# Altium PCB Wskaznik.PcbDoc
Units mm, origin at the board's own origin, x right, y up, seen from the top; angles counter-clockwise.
Board outline 100 x 60 mm, 2 copper layers (Top Layer, Bottom Layer); 40 components, 28 nets, 111 pads, 0 vias.
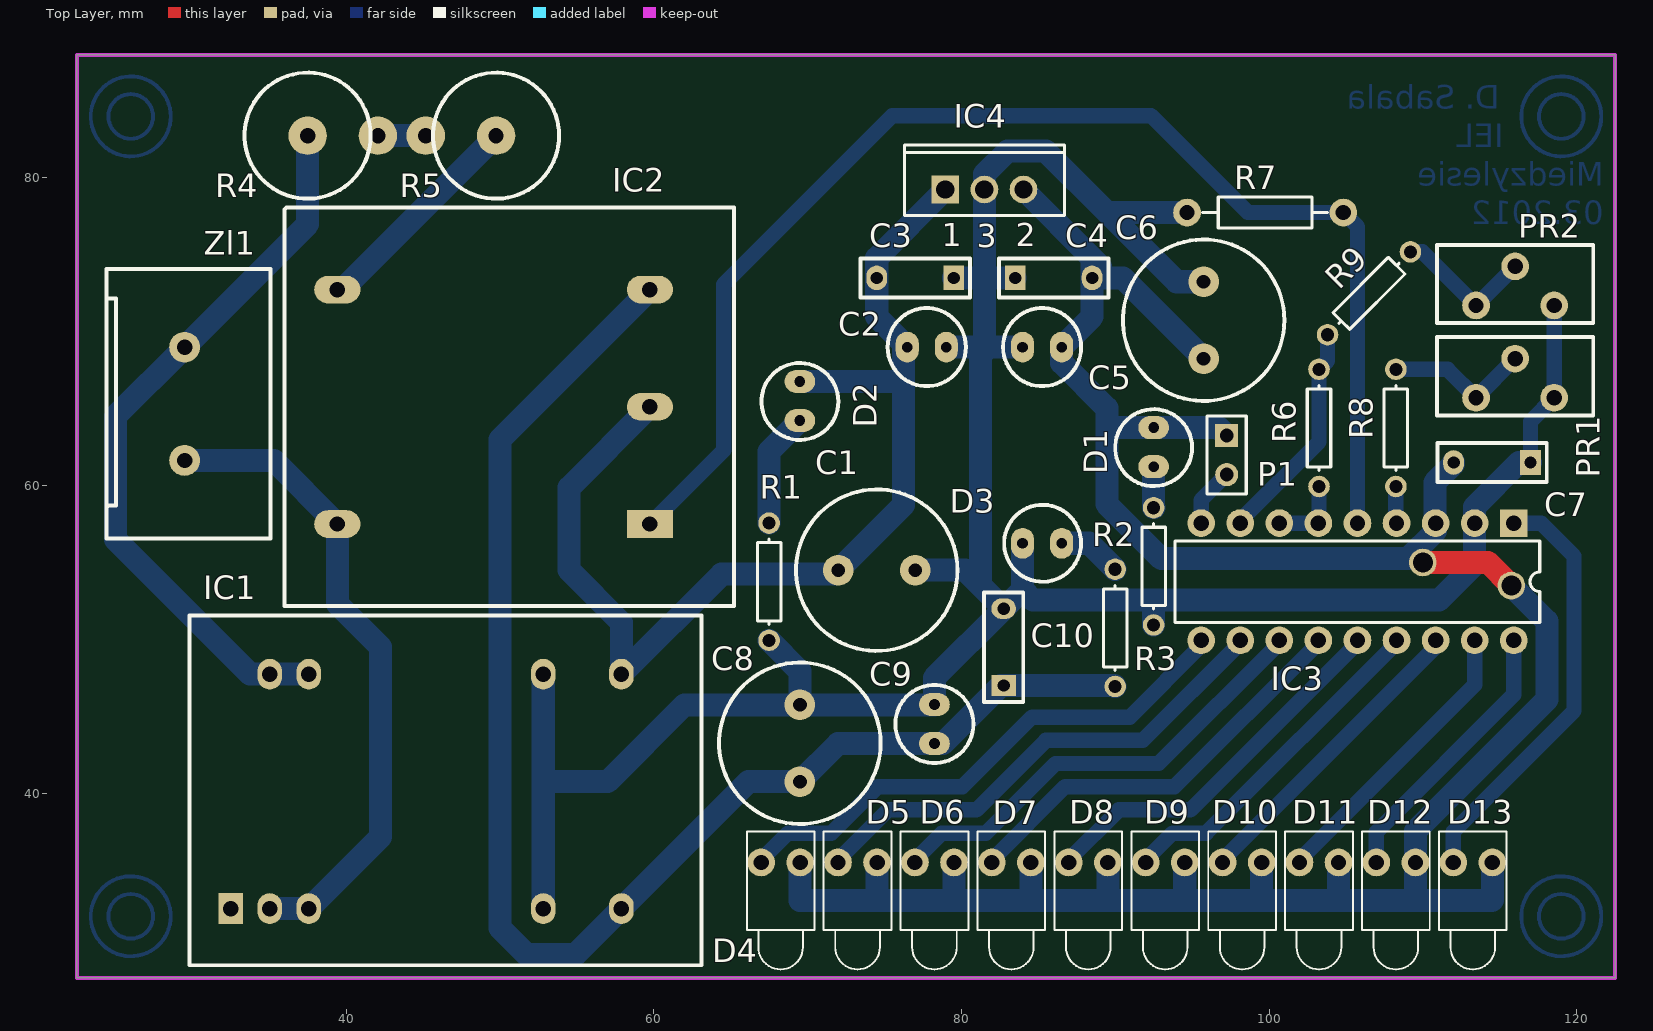
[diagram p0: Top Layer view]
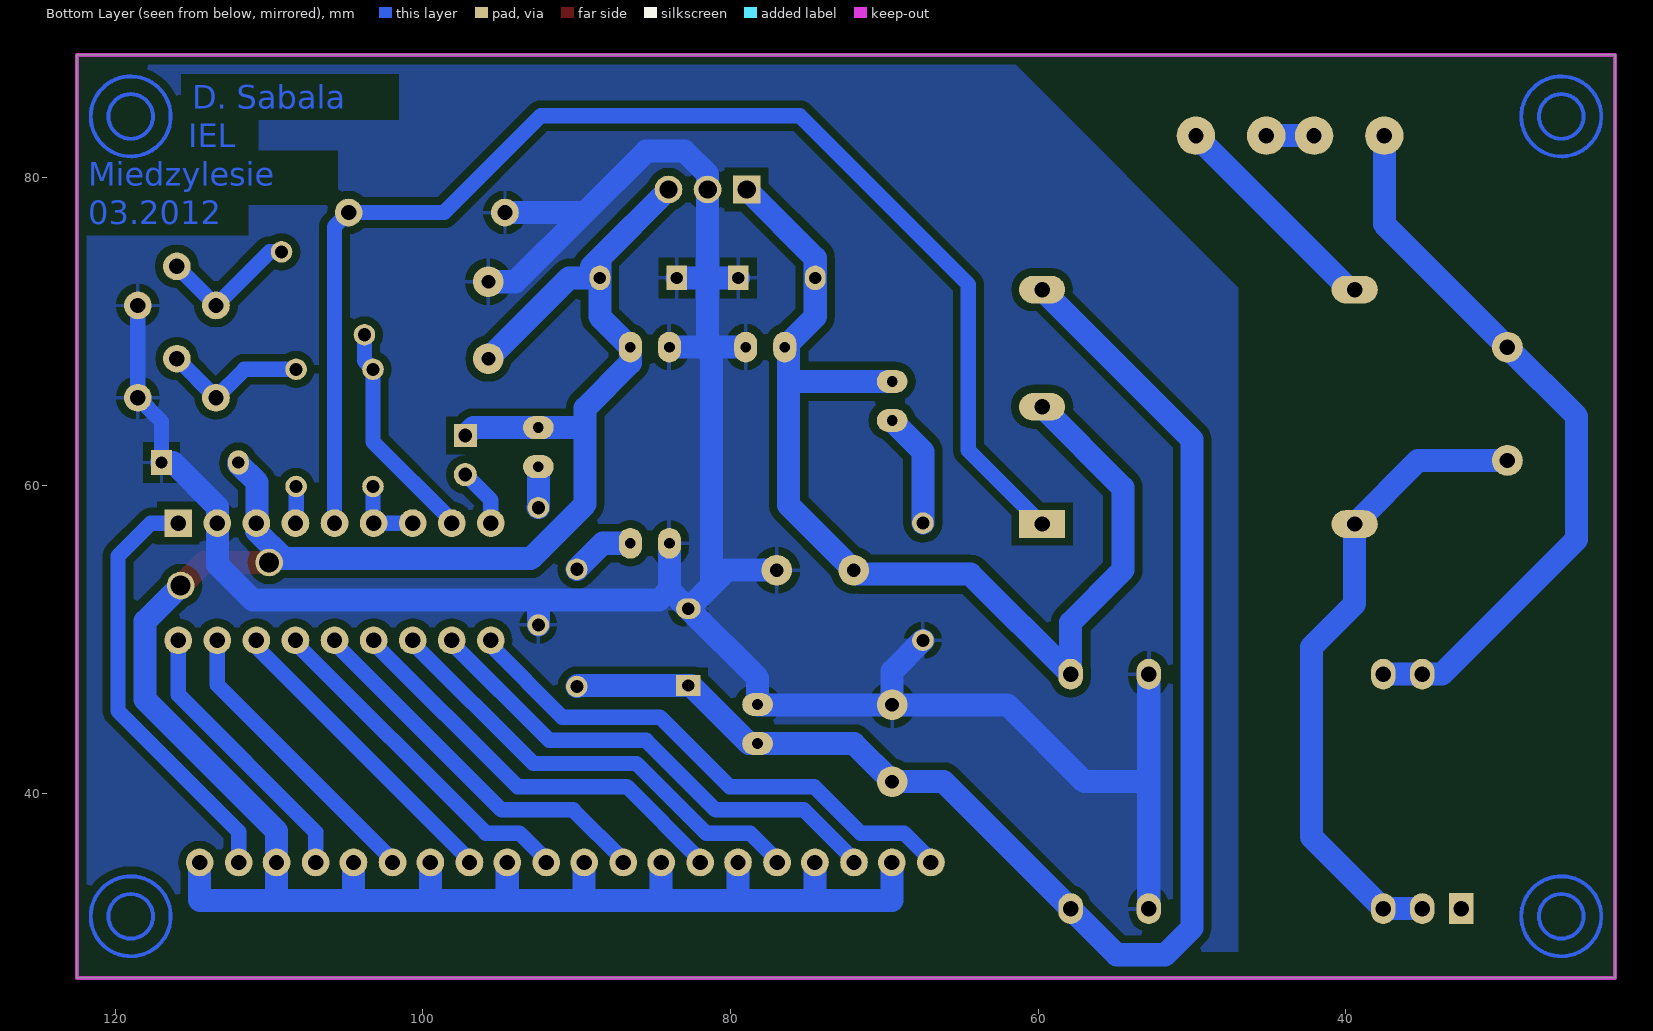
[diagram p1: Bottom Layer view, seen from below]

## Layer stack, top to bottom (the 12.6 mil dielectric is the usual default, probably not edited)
Top Layer: signal copper 0.0356
Dielectric: dielectric 0.32, FR-4, Dk 4.8
Bottom Layer: signal copper 0.0356

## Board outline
22.5,28 22.5,88 122.5,88 122.5,28

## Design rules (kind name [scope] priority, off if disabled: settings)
Clearance [All] p1: gap=0.508
LayerPairs [All] p1 off: enforce=TRUE
PolygonConnect [All] p1: connectstyle=Relief reliefconductorwidth=0.254 reliefentries=4 polygonreliefangle="90 Angle"
RoutingVias [All] p1: holewidth=0.711 width=1.27 viastyle="Through Hole" minholewidth=0.711 minwidth=1.27 maxholewidth=0.711 maxwidth=1.27
SilkscreenOverComponentPads [All] p1: minsilkscreentomaskgap=0.254
SolderMaskExpansion [All] p1: expansion=0.102
Width [All] p1: maxlimit=2 minlimit=0.254 preferedwidth=0.254
26 further rules are at their usual default settings.

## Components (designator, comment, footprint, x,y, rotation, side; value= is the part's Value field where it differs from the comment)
C1 "" RB5-10.5 74.5,54.5 r0 top
C2 "" "Elektrolit 2.5" 77.75,69 r0 top
C3 "" poliestrowy 77,73.5 r180 top
C4 "" poliestrowy 86,73.5 r0 top
C5 "" "Elektrolit 2.5" 85.25,69 r180 top
C6 "" RB5-10.5 95.75,70.75 r90 top
C7 "" poliestrowy 114.5,61.5 r180 top
C8 "" RB5-10.5 69.5,43.25 r270 top
C9 "" "Elektrolit 2.5" 78.25,44.5 r270 top
C10 "" poliestrowy 82.75,49.5 r90 top
D1 "Dioda LED" "dioda led" 92.5,62.5 r270 top
D2 "Dioda LED" "dioda led" 69.5,65.5 r270 top
D3 "Dioda LED" "dioda led" 85.25,56.25 r0 top
D4 "" LED-1 68.25,35.5 r270 top
D5 "" LED-1 73.25,35.5 r270 top
D6 "" LED-1 78.25,35.5 r270 top
D7 "" LED-1 83.25,35.5 r270 top
D8 "" LED-1 88.25,35.5 r270 top
D9 "" LED-1 93.25,35.5 r270 top
D10 "" LED-1 98.25,35.5 r270 top
D11 "" LED-1 103.25,35.5 r270 top
D12 "" LED-1 108.25,35.5 r270 top
D13 "" LED-1 113.25,35.5 r270 top
IC1 "TEN8-7223WI" TRACO-DIP24 32.5,32.5 r90 top
IC2 "LV 25-P" "DIP14 LEM NEW" 59.75,57.5 r180 top
IC3 "LM3914" DIP18 105.75,53.75 r180 top
IC4 "7805" ISOWATT220AB 81.5,79.25 r0 top
P1 "Jumper" HDR1X2 97.25,63.25 r270 top
PR1 "10k" "PCBComponent_1 - duplicate" 116,68.25 r90 top
PR2 "470" "PCBComponent_1 - duplicate" 116,74.25 r90 top
R1 "Rezystor" AXIAL-0.3 67.5,53.75 r90 top
R2 "Rezystor" AXIAL-0.3 92.5,54.75 r90 top
R3 "Rezystor" AXIAL-0.3 90,50.75 r90 top
R4 "Rezystor" "duzy pionowo" 37.5,82.75 r0 top
R5 "Rezystor" "duzy pionowo" 49.75,82.75 r180 top
R6 "Rezystor" AXIAL-0.3 103.25,63.75 r270 top
R7 "" AXIAL-0.4 99.75,77.75 r0 top
R8 "Rezystor" AXIAL-0.3 108.25,63.75 r270 top
R9 "Rezystor" AXIAL-0.3 106.5,72.5 r225 top
Zl1 "Złącze 7.3mm" "PCBComponent_1 - duplicate1" 29.5,69 r270 top

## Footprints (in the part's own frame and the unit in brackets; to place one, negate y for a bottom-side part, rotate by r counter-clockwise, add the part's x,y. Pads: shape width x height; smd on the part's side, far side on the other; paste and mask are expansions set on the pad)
AXIAL-0.3 [mm] "Axial Device, Thru-Hole; 2 Leads; 0.3 in Pin Spacing"
  round 1.4 hole 0.85: 1(-3.81,0) 2(3.81,0)
  silkscreen extent -2.77,-0.76 2.77,0.76
AXIAL-0.4 [mm] "Axial Device, Thru-Hole; 2 Leads; 0.4 in Pin Spacing"
  round 1.8 hole 1 unplated: 1(-5.08,0) 2(5.08,0)
  silkscreen extent -4.06,-1.02 4.06,1.02
"dioda led" [mm] "Radial Cap, Thru-Hole; 2 Leads; 0.1 in Pin Spacing"
  oval 1.5x2 hole 0.7: 1(-1.27,0) 2(1.27,0)
  silkscreen extent -2.47,-2.5 2.53,2.5
"DIP14 LEM NEW" [mm]
  rect 3x1.8 hole 1: 1(0,0)
  oval 3x1.8 hole 1: 4(0,-7.62) 7(0,-15.24) 8(20.32,-15.24) 14(20.32,0)
  silkscreen extent -5.46,-20.57 23.75,5.33
DIP18 [mm] "DIP; 18 Leads; Row Spacing 7.62 mm; Pitch 2.54 mm"
  rect 1.8x1.8 hole 1 unplated: 1(-10.16,-3.81)
  round 1.8 hole 1 unplated: 2(-7.62,-3.81) 3(-5.08,-3.81) 4(-2.54,-3.81) 5(0,-3.81) 6(2.54,-3.81) 7(5.08,-3.81) 8(7.62,-3.81) 9(10.16,-3.81) 10(10.16,3.81) 11(7.62,3.81) 12(5.08,3.81) 13(2.54,3.81) 14(0,3.81) 15(-2.54,3.81) 16(-5.08,3.81) 17(-7.62,3.81) 18(-10.16,3.81)
  silkscreen extent -11.85,-2.65 11.85,2.65
"duzy pionowo" [mm] "Axial Device, Thru-Hole; 2 Leads; 1.0 in Pin Spacing"
  round 2.5 hole 1: 1(0,0) 2(4.572,0)
  silkscreen extent -4.1,-4.1 4.1,4.1
"Elektrolit 2.5" [mm] "raster 2.5mm fi 5.08"
  oval 1.5x2 hole 0.7: 1(-1.27,0) 2(1.27,0)
  silkscreen extent -2.54,-2.54 2.54,2.54
HDR1X2 [mm] "Connector; Header; 2 Position"
  rect 1.5x1.5 hole 0.9: 1(0,0)
  round 1.5 hole 0.9: 2(2.54,0)
  silkscreen extent -1.27,-1.27 3.81,1.27
ISOWATT220AB [mm] "TO, Thru-Hole, Vertical, Heatsink Mounted; 3 In-Line Leads; Pitch 2.54 mm; Pin sequence 1, 3, 2"
  rect 1.8x1.8 hole 1.2: 1(-2.54,0)
  round 1.8 hole 1.2: 2(2.54,0) 3(0,0)
  silkscreen extent -5.2,-1.7 5.2,2.9
LED-1 [mm] "LED; 2 Leads"
  round 1.8 hole 1 unplated: 1(0,1.27) 2(0,-1.27)
  silkscreen extent -2,-2.2 6.95,2.2
"PCBComponent_1 - duplicate" [mm]
  round 1.8 hole 1 unplated: 1(-2.54,-2.54) 2(0,0) 3(-2.54,2.54)
  silkscreen extent -3.68,-5.08 1.4,5.08
"PCBComponent_1 - duplicate1" [mm]
  round 2 hole 1: 1(0,0) 2(7.366,0)
  silkscreen extent -5.08,-5.08 12.45,5.59
poliestrowy [mm] "Capacitor; 2 Leads"
  rect 1.35x1.6 hole 0.8: 1(-2.5,0)
  oval 1.35x1.6 hole 0.8: 2(2.5,0)
  silkscreen extent -3.56,-1.27 3.56,1.27
RB5-10.5 [mm] "Capacitor (Radial); 2 Leads"
  round 2 hole 0.9: 1(-2.5,0) 2(2.5,0)
  silkscreen extent -5.25,-5.25 5.25,5.25
TRACO-DIP24 [mm]
  rect 2x1.6 hole 1 unplated: 1(0,0)
  oval 2x1.6 hole 1 unplated: 2(0,-2.54) 3(0,-5.08) 9(0,-20.32) 11(0,-25.4) 14(15.24,-25.4) 16(15.24,-20.32) 22(15.24,-5.08) 23(15.24,-2.54)
  silkscreen extent -3.68,-30.61 19.05,2.67

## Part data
C1 C2 C5 C6 C8 C9: library part "Kondensator el."
C3 C10: library part Kondensator
C4 C7: library part Kondensator, "330nF"
D1 D2 D3: "LED"
D4 D5 D6 D7 D8 D9 D10 D11 D12 D13: library part LED1, "Typical RED GaAs LED"
IC1: library part "TEN 8-7223WI"
IC3: "LED BAR DRIVER"
IC4: library part L78M05CP, "Positive Voltage Regulator"
P1: library part "Header 2", "Header, 2-Pin"
PR1 PR2: library part "Potencjometr ELFA", "Potencjometr ELFA"
R7: library part Res2, "Resistor"

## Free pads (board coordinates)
  round 1.8 hole 1.3: 0(110,55) 1(115.75,53.5)

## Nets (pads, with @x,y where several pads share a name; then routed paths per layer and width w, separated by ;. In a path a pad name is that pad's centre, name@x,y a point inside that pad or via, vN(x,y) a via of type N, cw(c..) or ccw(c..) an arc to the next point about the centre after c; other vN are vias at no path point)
+5V: C4.2 C5.1 C6.1 C7.2 D1.1 D4.1 D5.1 D6.1 D7.1 D8.1 D9.1 D10.1 D11.1 D12.1 D13.1 IC3.3 IC4.2 P1.1 pad.0 pad.1 | length 171.4
  Top Layer w1.5: pad.0 114.25,55 pad.1
  Bottom Layer w1: IC3.3@110.83,57.402 IC3.3
  Bottom Layer w1.5: D4.1 69.52,33.02 74.635,33.02 ; D5.1 74.52,33.135 74.635,33.02 ; D6.1 79.52,33.25 79.75,33.02 ; IC4.2 88.5,74.79 ; D7.1 84.52,33.29 84.25,33.02 ; 89.04,74.25 88.5,74.79 ; D8.1 89.52,33.04 89.54,33.02 ; D9.1 94.52,33.04 94.5,33.02 ; C6.1 90.5,73.5 C4.2 ; P1.1 96.73,63.77 D1.1 89.46,63.77 ; D10.1 99.52,33.04 99.5,33.02 ; D11.1 104.52,33.25 104.75,33.02 ; pad.0 109.75,55.25 109.032,55.25 ; C7.2 112,61.421 110.789,60.211 110.789,57.442 110.83,57.402 110.83,57.048 109.032,55.25 ; D13.1 114.52,33.06 114.48,33.02 109.5,33.02 ; pad.1 118.068,51.182 118.068,46.082 109.52,37.534 D12.1 109.52,33.04 109.5,33.02 ; 74.635,33.02 79.75,33.02 ; 79.75,33.02 84.25,33.02 ; 84.25,33.02 89.54,33.02 ; C4.2 88.5,74.79 ; C4.2 88.5,70.98 C5.1 86.52,67.98 89.46,65.04 89.46,63.77 ; 89.46,63.77 89.46,58.79 93,55.25 109.032,55.25 ; 89.54,33.02 94.5,33.02 ; 94.5,33.02 99.5,33.02 ; 99.5,33.02 104.75,33.02 ; 104.75,33.02 109.5,33.02
+15V: C1.1 C2.1 C3.2 D2.1 IC1.14 IC2.4 IC4.1 | length 73.9
  Bottom Layer w1.5: IC2.4 54.5,59.87 54.5,54.5 57.9,51.1 IC1.14 64.41,54.25 71.75,54.25 C1.1 76.23,58.73 76.23,66.75 ; D2.1 76.21,66.77 76.23,66.75 ; IC4.1 74.5,74.79 C3.2 74.5,70.98 C2.1 76.23,68.75 76.23,66.75
-15V: C8.2 C9.2 C10.1 IC1.11 IC2.7 R3.1 | length 93.5
  Bottom Layer w1.5: IC2.7 50,62.99 50,31.25 51.75,29.5 54.9,29.5 IC1.11 66.15,40.75 C8.2 71.98,43.23 C9.2 78.8,43.23 82.57,47 C10.1 89.94,47 R3.1
GND: C1.2 C2.2 C3.1 C4.1 C5.2 C6.2 C7.1 C8.1 C9.1 C10.2 D3.1 IC1.9 IC1.16 IC3.2 IC4.3 PR1.1 PR2.1 R1.1 R2.1 R7.1 | length 178.9
  Bottom Layer w1: C7.1 117,64.17 PR1.1 PR2.1
  Bottom Layer w1.5: IC1.9 52.82,40.75 ; IC1.16 52.82,40.75 ; R1.1 69.5,47.94 C8.1 ; C1.2 80.25,54.5 81.125,53.625 ; C2.2 81.25,69 ; C3.1 81.5,73.5 ; C4.1 81.5,73.5 ; D3.1 83.98,53.23 ; C5.2 81.75,69 81.5,68.75 ; R2.1 92.5,52.302 92.25,52.552 ; R7.1 89.5,77.75 ; C6.2@95.67,73.33 C6.2 94,73.25 89.5,77.75 ; C7.1 116.25,61.5 113.37,58.62 IC3.2 113.37,54.87 111.052,52.552 92.25,52.552 ; 52.82,40.75 57,40.75 62,45.75 C8.1 ; C8.1 78.23,45.75 C9.1 78.25,47.5 C10.2 ; 81.125,53.625 C10.2 ; 81.125,53.625 81.25,53.75 81.25,69 ; 81.25,69 81.5,68.75 ; 81.5,68.75 81.5,73.5 ; 81.5,73.5 IC4.3 81.5,80.25 83,81.75 85.5,81.75 89.5,77.75 ; C10.2 83.98,53.23 ; 83.98,53.23 84.658,52.552 92.25,52.552
NetD1_2: D1.2 R2.2 | length 2.7
  Bottom Layer w1.5: D1.2 92.5,58.59 R2.2@92.515,58.575
NetD2_2: D2.2 R1.2 | length 7.5
  Bottom Layer w1.5: R1.2 67.5,62.23 D2.2
NetD3_2: D3.2 R3.2 | length 4.2
  Bottom Layer w1.5: D3.2 88.31,56.25 R3.2
NetD4_2: D4.2 IC3.10 | length 34.9
  Bottom Layer w1: D4.2 66.98,35.658 68.73,37.408 71.553,37.408 74.569,40.424 80.075,40.424 84.599,44.948 90.948,44.948 95.59,49.59 IC3.10
NetD5_2: D5.2 IC3.11 | length 32.3
  Bottom Layer w1: D5.2 71.98,35.658 75.238,38.916 80.972,38.916 85.496,43.44 91.788,43.44 98.13,49.782 IC3.11
NetD6_2: D6.2 IC3.12 | length 29.9
  Bottom Layer w1: D6.2 76.98,35.658 78.73,37.408 81.597,37.408 86.121,41.932 92.82,41.932 100.67,49.782 IC3.12
NetD7_2: D7.2 IC3.13 | length 27.4
  Bottom Layer w1: D7.2 81.98,35.658 86.746,40.424 93.852,40.424 103.21,49.782 IC3.13
NetD8_2: D8.2 IC3.14 | length 24.9
  Bottom Layer w1: D8.2 86.98,35.658 90.238,38.916 94.884,38.916 105.75,49.782 IC3.14
NetD9_2: D9.2 IC3.15 | length 22.5
  Bottom Layer w1: D9.2 91.98,35.658 93.73,37.408 95.916,37.408 108.29,49.782 IC3.15
NetD10_2: D10.2 IC3.16 | length 20.2
  Bottom Layer w1: D10.2 96.98,35.658 110.83,49.508 IC3.16
NetD11_2: D11.2 IC3.17 | length 19.2
  Bottom Layer w1: D11.2 101.98,35.658 113.37,47.048 IC3.17
NetD12_2: D12.2 IC3.18 | length 18.1
  Bottom Layer w1: D12.2 106.98,37.48 115.91,46.41 IC3.18
NetD13_2: D13.2 IC3.1 | length 28
  Bottom Layer w1: D13.2 111.98,37.508 119.826,45.354 119.826,55.424 117.69,57.56 IC3.1
NetIC2_1: IC2.1 IC3.5 R7.2 | length 85.7
  Bottom Layer w1: IC2.1 64.541,62.291 64.541,73.076 75.514,84.049 92.329,84.049 98.628,77.75 R7.2 105.75,76.83 IC3.5 IC3.5@105.83,57.64
NetIC2_8: IC2.8 R5.1 | length 14.5
  Bottom Layer w1.5: IC2.8 39.74,72.74 R5.1
NetIC3_4: IC3.4 R8.2 | length 2.4
  Bottom Layer w1: R8.2 108.25,57.6 IC3.4
NetIC3_6: IC3.6 IC3.7 R6.2 | length 4.9
  Bottom Layer w1: IC3.7 IC3.6 103.25,57.6 R6.2
NetIC3_8: IC3.8 R6.1 R9.2 | length 14.6
  Bottom Layer w1: IC3.8 98.13,57.718 103.25,62.838 R6.1 103.806,68.116 R9.2
NetIC3_9: IC3.9 P1.2 | length 3.8
  Bottom Layer w1: IC3.9 95.59,59.05 P1.2
NetPR1_2: PR1.2 PR1.3 R8.1 | length 9.6
  Bottom Layer w1: R8.1 111.61,67.56 PR1.3 PR1.2
NetPR2_2: PR2.2 PR2.3 R9.1 | length 9.3
  Bottom Layer w1: R9.1 109.976,75.194 PR2.3 PR2.2
NetR4_2: R4.2 R5.2 | length 3.1
  Bottom Layer w1.5: R4.2 R5.2
WE+: IC1.22 IC1.23 R4.1 Zl1.1 | length 47.6
  Bottom Layer w1.5: R4.1 37.5,77 Zl1.1 25,64.5 25,56.5 33.76,47.74 IC1.23 IC1.22
WE-: IC1.2 IC1.3 IC2.14 Zl1.2 | length 42.3
  Bottom Layer w1.5: Zl1.2 35.296,61.634 IC2.14 39.43,52.32 42.25,49.5 42.25,37.17 IC1.3 IC1.2
pads on no net: IC1.1
copper on no net: | length 101.8
  Bottom Layer w0.254: 27.45,32 ccw(c26,32) 27.45,32 ; 27.45,84 ccw(c26,84) 27.45,84 ; 28.6,32 ccw(c26,32) 28.6,32 ; 28.6,84 ccw(c26,84) 28.6,84 ; 120.45,32 ccw(c119,32) 120.45,32 ; 120.45,84 ccw(c119,84) 120.45,84 ; 121.6,32 ccw(c119,32) 121.6,32 ; 121.6,84 ccw(c119,84) 121.6,84

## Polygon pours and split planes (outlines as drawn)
GND on Bottom Layer "Bottom Layer-No Net" (solid, remove dead copper, pour order 4): 61.873,87.656 61.772,87.656 46.989,72.874 46.989,29.694 122.579,29.694 122.579,87.707

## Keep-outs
Keep-Out Layer:
  the board outline again, w0.254

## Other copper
Bottom Layer:
  text "D. Sabala" at 115,84.5 h1.52
  text "IEL" at 115.25,82 h1.52
  text "Miedzylesie" at 121.75,79.5 h1.52
  text "03.2012" at 121.75,77 h1.52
